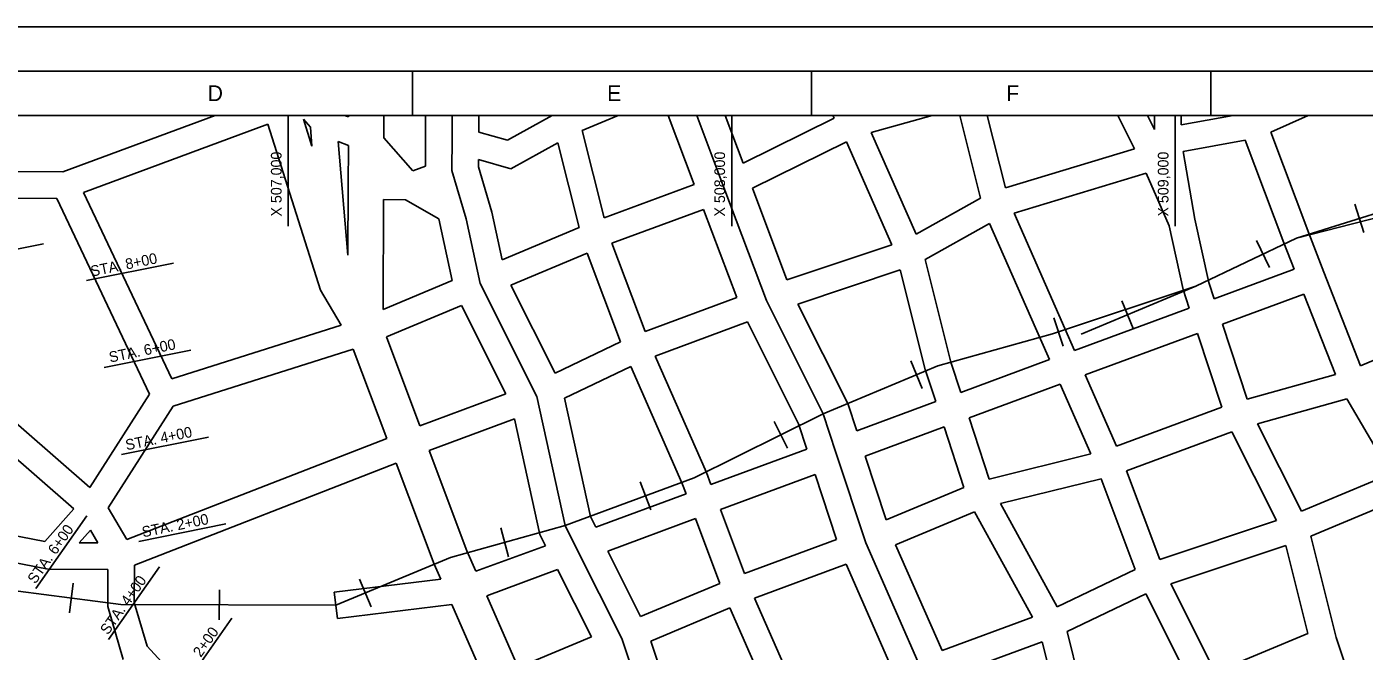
# Model space of a CAD drawing. Extents: x 503330 to 511530, y 1310349 to 1316149.
# Drawn here: x 506410 to 509426, y 1314740 to 1316149 of the extents above; entities that cross this region are included whole.
import ezdxf

# ---------------------------------------------------------------- set-up
doc = ezdxf.new("R2010")
doc.units = 0
for name, color, linetype in [('G-ANNO-TTLB', 7, 'Continuous'), ('Level 13', 7, 'Continuous'), ('Level 14', 7, 'Continuous'), ('Level 2', 7, 'Continuous'), ('Level 23', 7, 'Continuous'), ('Level 3', 7, 'Continuous'), ('Level 32', 7, 'Continuous'), ('Level 37', 7, 'Continuous'), ('Level 56', 7, 'Continuous'), ('Level 58', 7, 'Continuous')]:
    doc.layers.add(name, color=color, linetype=linetype)

msp = doc.modelspace()

# ---------------------------------------------------------------- linework, layer by layer
at = {"layer": 'G-ANNO-TTLB'}
for p, q in [((511430.3, 1316048.5), (503430.3, 1316048.5)), ((507280.3, 1315948.5), (507280.3, 1316048.5)), ((508180.3, 1315948.5), (508180.3, 1316048.5)), ((509080.3, 1315948.5), (509080.3, 1316048.5)), ((503680.3, 1315948.5), (511330.3, 1315948.5))]:
    msp.add_line(p, q, dxfattribs=at)
for points in [[(503330.3, 1310348.5), (511530.3, 1310348.5), (511530.3, 1316148.5), (503330.3, 1316148.5)], [(503330.3, 1310348.5), (511530.3, 1310348.5), (511530.3, 1316148.5), (503330.3, 1316148.5)], [(503330.3, 1316148.5), (511530.3, 1316148.5), (511530.3, 1310348.5), (503330.3, 1310348.5)]]:
    msp.add_lwpolyline(points, close=True, dxfattribs=at)
at = {"layer": 'Level 13'}
for p, q in [((507369.4, 1315897.1), (507369.6, 1315948.5)), ((507982.4, 1315785.7), (507921.1, 1315948.5)), ((507369.1, 1315824.3), (507369.4, 1315897.1)), ((507401, 1315715.2), (507369.1, 1315824.3)), ((508078.3, 1315530.8), (507982.4, 1315785.7)), ((507432.7, 1315569.6), (507401, 1315715.2)), ((507560.9, 1315314.6), (507432.7, 1315569.6)), ((508206.5, 1315275.9), (508078.3, 1315530.8)), ((507624.4, 1315023.6), (507560.9, 1315314.6)), ((508235.2, 1315188.1), (508206.5, 1315275.9)), ((508302.2, 1314984.7), (508235.2, 1315188.1)), ((507650.4, 1314972.2), (507624.4, 1315023.6)), ((508430.3, 1314693.3), (508302.2, 1314984.7)), ((507752.6, 1314768.6), (507650.4, 1314972.2)), ((507848.3, 1314477.4), (507752.6, 1314768.6))]:
    msp.add_line(p, q, dxfattribs=at)
at = {"layer": 'Level 14'}
for p, q in [((507309.4, 1315897.3), (507309.6, 1315948.5)), ((507429.5, 1315911.1), (507429.6, 1315948.5)), ((507915.6, 1315792.9), (507857, 1315948.5)), ((508025.8, 1315840.7), (507985.2, 1315948.5)), ((507309.2, 1315834.1), (507309.4, 1315897.3)), ((507429.2, 1315832.8), (507429.2, 1315848.8)), ((507459.2, 1315730), (507429.2, 1315832.8)), ((508124.7, 1315577.9), (508047, 1315784.3)), ((508011.5, 1315538), (507936.7, 1315736.7)), ((507370, 1315575.9), (507339.5, 1315715.6)), ((507482.5, 1315622.9), (507459.2, 1315730)), ((507601.6, 1315367.3), (507501.7, 1315565.9)), ((507490.8, 1315320.6), (507390.8, 1315519.6)), ((508262.1, 1315298.8), (508149.4, 1315522.9)), ((508150.9, 1315252.9), (508035.3, 1315482.9)), ((507681.4, 1315043.8), (507623.1, 1315311.1)), ((508282.2, 1315237.4), (508262.1, 1315298.8)), ((507567.4, 1315003.3), (507510.6, 1315264)), ((508169.5, 1315195.9), (508150.9, 1315252.9)), ((508348.4, 1315036.5), (508300.9, 1315180.4)), ((508236.6, 1314992.3), (508188.3, 1315138.8)), ((507693.4, 1315020.1), (507681.4, 1315043.8)), ((507580.1, 1314978.2), (507567.4, 1315003.3)), ((507794.6, 1314818.7), (507720.5, 1314966.1)), ((508474.6, 1314741.8), (508369.7, 1314980.3)), ((507683.6, 1314772.3), (507607.3, 1314924.3)), ((508361.9, 1314699.9), (508258, 1314936.2)), ((507895.3, 1314526.8), (507817.5, 1314763.2))]:
    msp.add_line(p, q, dxfattribs=at)
at = {"layer": 'Level 2'}
for p, q in [((507000, 1315698.5), (507000, 1315948.5)), ((508000, 1315698.5), (508000, 1315948.5)), ((509000, 1315698.5), (509000, 1315948.5))]:
    msp.add_line(p, q, dxfattribs=at)
at = {"layer": 'Level 23'}
for p, q in [((507135.9, 1315945), (507135.9, 1315948.5)), ((507215.7, 1315897.8), (507215.9, 1315948.5)), ((507073.1, 1315554.4), (506953.9, 1315928.7)), ((507053.6, 1315879.2), (507034.2, 1315939.9)), ((507135.6, 1315880.9), (507135.3, 1315788.9)), ((507134.7, 1315633.2), (507135.3, 1315788.9)), ((507214.2, 1315510.8), (507215.2, 1315758.6)), ((507119.4, 1315475.6), (507073.1, 1315554.4)), ((507296.9, 1315248.7), (507221.6, 1315448.9)), ((507222.1, 1315220.2), (507146.5, 1315421.3)), ((507402.9, 1314966.9), (507318, 1315192.5)), ((507328.8, 1314936.7), (507243.2, 1315164.1)), ((507423.4, 1314920.4), (507402.9, 1314966.9)), ((507343.8, 1314902.7), (507328.8, 1314936.7)), ((507518.7, 1314703.4), (507447.5, 1314865.4)), ((507457.7, 1314643.5), (507369, 1314845.3))]:
    msp.add_line(p, q, dxfattribs=at)
at = {"layer": 'Level 32'}
for p, q in [((506834.9, 1315948.5), (506492, 1315821.3)), ((507135.9, 1315945), (507126.6, 1315948.5)), ((507494.7, 1315892.5), (507595.1, 1315948.5)), ((507663.2, 1315914.7), (507744.1, 1315948.5)), ((508231.3, 1315942.6), (508227.8, 1315948.5)), ((508314.9, 1315910.4), (508452.4, 1315948.5)), ((508561, 1315762), (508514.4, 1315948.5)), ((508617.1, 1315784.9), (508576.3, 1315948.5)), ((508908.4, 1315873.2), (508870.5, 1315948.5)), ((508953.7, 1315916.6), (508937.6, 1315948.5)), ((508953.7, 1315916.6), (508953.8, 1315948.5)), ((509013.8, 1315927.1), (509013.8, 1315948.5)), ((509013.8, 1315927.1), (509130.6, 1315948.5)), ((509215.5, 1315910.8), (509300.2, 1315948.5)), ((506953.9, 1315928.7), (506538.4, 1315774.5)), ((507049.9, 1315922.1), (507034.2, 1315939.9)), ((507049.9, 1315922.1), (507053.6, 1315879.2)), ((508025.8, 1315840.7), (508231.3, 1315942.6)), ((507135.6, 1315880.9), (507112.9, 1315889.5)), ((507112.9, 1315889.5), (507134.7, 1315633.2)), ((507281, 1315823.6), (507215.7, 1315897.8)), ((507429.5, 1315911.1), (507494.7, 1315892.5)), ((507502.1, 1315827.9), (507608.2, 1315887.1)), ((507656.1, 1315695.5), (507608.2, 1315887.1)), ((507712.4, 1315717.5), (507663.2, 1315914.7)), ((508047, 1315784.3), (508258.7, 1315889.2)), ((508360.8, 1315656.7), (508258.7, 1315889.2)), ((508415.7, 1315681), (508314.9, 1315910.4)), ((509018.3, 1315866.9), (509158.2, 1315892.6)), ((509245.4, 1315660.9), (509158.2, 1315892.6)), ((509301.3, 1315682.7), (509215.5, 1315910.8)), ((508617.1, 1315784.9), (508908.4, 1315873.2)), ((509044.7, 1315714.9), (509018.3, 1315866.9)), ((507281, 1315823.6), (507309.2, 1315834.1)), ((507429.2, 1315848.8), (507502.1, 1315827.9)), ((509418, 1315383.9), (510463.1, 1315829.3)), ((506492, 1315821.3), (506179.7, 1315822.5)), ((508636.7, 1315728.1), (508934.4, 1315818.4)), ((508986.5, 1315699.8), (508934.4, 1315818.4)), ((506737.4, 1315354.3), (506538.4, 1315774.5)), ((507712.4, 1315717.5), (507915.6, 1315792.9)), ((506478.3, 1315761.4), (506172.1, 1315762.5)), ((506687.3, 1315320), (506478.3, 1315761.4)), ((507215.2, 1315758.6), (507264.2, 1315758.4)), ((507339.5, 1315715.6), (507264.2, 1315758.4)), ((507730.1, 1315660.1), (507936.7, 1315736.7)), ((508415.7, 1315681), (508561, 1315762)), ((508751.2, 1315467.8), (508636.7, 1315728.1)), ((509075.9, 1315571.5), (509044.7, 1315714.9)), ((507482.5, 1315622.9), (507656.1, 1315695.5)), ((508436.2, 1315623.7), (508581.5, 1315704.8)), ((508696.2, 1315443.6), (508581.5, 1315704.8)), ((509018, 1315555.7), (508986.5, 1315699.8)), ((509335.5, 1315595), (509301.3, 1315682.7)), ((507804.9, 1315461.4), (507730.1, 1315660.1)), ((508124.7, 1315577.9), (508360.8, 1315656.7)), ((509268.5, 1315601.6), (509245.4, 1315660.9)), ((507501.7, 1315565.9), (507674.3, 1315638)), ((507749.6, 1315438.1), (507674.3, 1315638)), ((508494, 1315392.3), (508436.2, 1315623.7)), ((508149.4, 1315522.9), (508380.3, 1315600)), ((508436.3, 1315375.6), (508380.3, 1315600)), ((509088.1, 1315534.8), (509268.5, 1315601.6)), ((509418, 1315383.9), (509335.5, 1315595)), ((507214.2, 1315510.8), (507370, 1315575.9)), ((509031.7, 1315514), (509018, 1315555.7)), ((509088.1, 1315534.8), (509075.9, 1315571.5)), ((507804.9, 1315461.4), (508011.5, 1315538)), ((509106.8, 1315477.8), (509290.4, 1315545.7)), ((509361.3, 1315364.2), (509290.4, 1315545.7)), ((507221.6, 1315448.9), (507390.8, 1315519.6)), ((508772.8, 1315418.6), (509031.7, 1315514)), ((507119.4, 1315475.6), (506737.4, 1315354.3)), ((507827.6, 1315405.8), (508035.3, 1315482.9)), ((508772.8, 1315418.6), (508751.2, 1315467.8)), ((509162.3, 1315308.9), (509106.8, 1315477.8)), ((507601.6, 1315367.3), (507749.6, 1315438.1)), ((508716.4, 1315397.8), (508696.2, 1315443.6)), ((508797, 1315363.6), (509050.5, 1315457)), ((509105.2, 1315290.5), (509050.5, 1315457)), ((507146.5, 1315421.3), (506740.9, 1315292.5)), ((507943.1, 1315142.9), (507827.6, 1315405.8)), ((507623.1, 1315311.1), (507772.3, 1315382.4)), ((507887.6, 1315120.2), (507772.3, 1315382.4)), ((508460.2, 1315303.1), (508436.3, 1315375.6)), ((508516.5, 1315323.9), (508494, 1315392.3)), ((508516.5, 1315323.9), (508716.4, 1315397.8)), ((508867.8, 1315202.4), (508797, 1315363.6)), ((509162.3, 1315308.9), (509361.3, 1315364.2)), ((506687.3, 1315320), (506552.6, 1315109.4)), ((507296.9, 1315248.7), (507490.8, 1315320.6)), ((508535.3, 1315266.9), (508740.6, 1315342.8)), ((508809.9, 1315185), (508740.6, 1315342.8)), ((506740.9, 1315292.5), (506594.3, 1315063.3)), ((508282.2, 1315237.4), (508460.2, 1315303.1)), ((508867.8, 1315202.4), (509105.2, 1315290.5)), ((509185.9, 1315253.2), (509387.1, 1315309.1)), ((509486.3, 1315140), (509387.1, 1315309.1)), ((507318, 1315192.5), (507510.6, 1315264)), ((508580.7, 1315128.5), (508535.3, 1315266.9)), ((509285.2, 1315055.9), (509185.9, 1315253.2)), ((508300.9, 1315180.4), (508478.9, 1315246.1)), ((508523.8, 1315109.8), (508478.9, 1315246.1)), ((508890.5, 1315146.8), (509128, 1315234.9)), ((509228.6, 1315034.9), (509128, 1315234.9)), ((507222.1, 1315220.2), (506636.2, 1314991.9)), ((507953.3, 1315116.1), (508169.5, 1315195.9)), ((507243.2, 1315164.1), (506653.2, 1314934.1)), ((508580.7, 1315128.5), (508809.9, 1315185)), ((507953.3, 1315116.1), (507943.1, 1315142.9)), ((507974.5, 1315060), (508188.3, 1315138.8)), ((508965.6, 1314947.1), (508890.5, 1315146.8)), ((509285.2, 1315055.9), (509486.3, 1315140)), ((507897, 1315095.3), (507887.6, 1315120.2)), ((508348.4, 1315036.5), (508523.8, 1315109.8)), ((508606.1, 1315073), (508833.1, 1315128.9)), ((508909.9, 1314924.7), (508833.1, 1315128.9)), ((507693.4, 1315020.1), (507897, 1315095.3)), ((508733.9, 1314840.6), (508606.1, 1315073)), ((509306.3, 1314999.7), (509514, 1315086.5)), ((506516.5, 1315061.3), (506450.8, 1314987.9)), ((506636.2, 1314991.9), (506594.3, 1315063.3)), ((508028.9, 1314915.2), (507974.5, 1315060)), ((508369.7, 1314980.3), (508547.6, 1315054.7)), ((508678.2, 1314817.3), (508547.6, 1315054.7)), ((506273.6, 1315021.9), (506450.8, 1314987.9)), ((506554.1, 1315013.3), (506528.7, 1314985)), ((506570.8, 1314984.8), (506554.1, 1315013.3)), ((507720.5, 1314966.1), (507918.2, 1315039.2)), ((507973, 1314893.2), (507918.2, 1315039.2)), ((508965.6, 1314947.1), (509228.6, 1315034.9)), ((506570.8, 1314984.8), (506528.7, 1314985)), ((508028.9, 1314915.2), (508236.6, 1314992.3)), ((509363.4, 1314771), (509306.3, 1314999.7)), ((506263, 1314962.8), (506459, 1314925.2)), ((507423.4, 1314920.4), (507580.1, 1314978.2)), ((508990, 1314892.1), (509249.7, 1314978.7)), ((509299.2, 1314780.4), (509249.7, 1314978.7)), ((506593.2, 1314924.7), (506459, 1314925.2)), ((506592.9, 1314841.3), (506593.2, 1314924.7)), ((506652.9, 1314849.8), (506653.2, 1314934.1)), ((507447.5, 1314865.4), (507607.3, 1314924.3)), ((508051.5, 1314859.6), (508258, 1314936.2)), ((508733.9, 1314840.6), (508909.9, 1314924.7)), ((507103.5, 1314873.5), (507343.8, 1314902.7)), ((507794.6, 1314818.7), (507973, 1314893.2)), ((509090.1, 1314693), (508990, 1314892.1)), ((507103.5, 1314873.5), (507110.8, 1314813.9)), ((508756.3, 1314784.8), (508934.1, 1314869.8)), ((509034, 1314671), (508934.1, 1314869.8)), ((506627.9, 1314721.2), (506592.9, 1314841.3)), ((506681.6, 1314751.5), (506652.9, 1314849.8)), ((507110.8, 1314813.9), (507369, 1314845.3)), ((507817.5, 1314763.2), (507995.7, 1314837.7)), ((508099.1, 1314602.4), (507995.7, 1314837.7)), ((508155.4, 1314623.3), (508051.5, 1314859.6)), ((508474.6, 1314741.8), (508678.2, 1314817.3)), ((507518.7, 1314703.4), (507683.6, 1314772.3)), ((508805.9, 1314586.4), (508756.3, 1314784.8)), ((509090.1, 1314693), (509299.2, 1314780.4)), ((509445.3, 1314522), (509363.4, 1314771)), ((507215.1, 1314173.7), (506681.6, 1314751.5)), ((508494.2, 1314685.1), (508700.3, 1314761.5)), ((508749.3, 1314565.4), (508700.3, 1314761.5))]:
    msp.add_line(p, q, dxfattribs=at)
for points in [[(506516.5, 1315061.3), (506110.8, 1315415.5), (506112.2, 1315796)], [(506552.6, 1315109.4), (506170.9, 1315442.7), (506172.1, 1315762.5)]]:
    msp.add_lwpolyline(points, dxfattribs=at)
at = {"layer": 'Level 37'}
for p, q in [((510155.9, 1315948.5), (509273.4, 1315671.8)), ((509405.5, 1315748.5), (509425.7, 1315684.3)), ((509047, 1315563.6), (509273.4, 1315671.8)), ((509183.5, 1315666.2), (509212.5, 1315605.4)), ((509047, 1315563.6), (508788.3, 1315455.5)), ((508879.5, 1315530.1), (508905.5, 1315468)), ((508747.6, 1315428.2), (508726.3, 1315492.1)), ((508429.6, 1315332.6), (508403.7, 1315394.8)), ((508125.5, 1315198.1), (508095.6, 1315258.5)), ((507817.4, 1315059.3), (507794, 1315122.4)), ((507497.1, 1314953.3), (507479.1, 1315018.2)), ((506506.4, 1314826.6), (506515, 1314893.4)), ((507186.9, 1314840.6), (507160.9, 1314902.7)), ((506844.5, 1314811.1), (506844.8, 1314878.4))]:
    msp.add_line(p, q, dxfattribs=at)
for points in [[(509273.4, 1315671.8), (510354.6, 1315948.5)], [(503680.3, 1313141.4), (503840.6, 1313353.6), (504337.7, 1314012.3), (504359.8, 1314041.6), (504943.9, 1314815.6), (505235, 1314959.9), (505912.9, 1314921), (506042, 1314920.5), (506332.5, 1314883), (506622.9, 1314845.6), (507107.2, 1314843.7), (507365.8, 1314951.8), (507624.4, 1315023.6), (507915.4, 1315131.5), (508206.5, 1315275.9), (508465.2, 1315384), (508723.7, 1315455.7), (509047, 1315563.6)]]:
    msp.add_lwpolyline(points, dxfattribs=at)
at = {"layer": 'Level 56'}
for p, q in [((506545.3, 1315576.2), (506741.4, 1315615.5)), ((506584.6, 1315380.1), (506780.7, 1315419.4)), ((506623.9, 1315184), (506820, 1315223.3)), ((506431, 1314881.7), (506546.1, 1315045.2)), ((506663.2, 1314987.9), (506859.3, 1315027.2)), ((506594.6, 1314766.6), (506709.7, 1314930.2)), ((506758.1, 1314651.5), (506873.2, 1314815.1))]:
    msp.add_line(p, q, dxfattribs=at)
at = {"layer": 'Level 58'}
msp.add_line((505406.1, 1315449.9), (506448.3, 1315658.8), dxfattribs=at)

# ---------------------------------------------------------------- texts
at = {"layer": 'G-ANNO-TTLB'}
for s, p in [('D', (506818.3, 1315980.7)), ('E', (507719.1, 1315980.7)), ('F', (508619.1, 1315980.7))]:
    msp.add_text(s, height=35.7, dxfattribs=at).set_placement(p)
at = {"layer": 'Level 3'}
for s, p in [('X 507,000', (506985, 1315720.5)), ('X 508,000', (507985, 1315720.5)), ('X 509,000', (508985, 1315720.5))]:
    msp.add_text(s, height=24, rotation=90, dxfattribs=at).set_placement(p)
at = {"layer": 'Level 56'}
for s, rotation, p in [('STA. 8+00', 11.5333, (506556.8, 1315584.9)), ('STA. 6+00', 11.5333, (506598.3, 1315391.1)), ('STA. 4+00', 11.5333, (506635.5, 1315193.2)), ('STA. 2+00', 11.5333, (506672.6, 1314996.9)), ('STA. 6+00', 54.8605, (506429.7, 1314890.4)), ('STA. 4+00', 54.6639, (506593.5, 1314775.5)), ('STA. 2+00', 54.7657, (506756.6, 1314659.4))]:
    msp.add_text(s, height=24, rotation=rotation, dxfattribs=at).set_placement(p)

doc.saveas('drawing.dxf')
